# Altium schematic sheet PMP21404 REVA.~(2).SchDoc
size 431 x 279 mm; Date: Not shown in title block; ApprovedBy: Not shown in title block; CheckedBy: Not shown in title block; Author: Not shown in title block; CompanyName: Not shown in title block; Engineer: Not shown in title block; Organization: Not shown in title block; Address1: Not shown in title block; Address2: Not shown in title block; Address3: Not shown in title block; Address4: Not shown in title block; DocumentNumber: 1; Revision: Use project parameter SCH_Rev; SheetNumber: 1; SheetTotal: 1; PageSetup: Record=PageOptions¦CenterHorizontal=True¦CenterVertical=True¦PrintScale=1.00¦XCorrection=1.00¦YCorrection=1.00¦PrintKind=0¦BorderSize=5000000¦LeftOffset=0¦BottomOffset=0¦Orientation=2¦PaperLength=1000¦PaperWidth=1000¦Scale=100¦PaperSource=15¦PrintQuality=600¦MediaType=1¦DitherType=10¦PaperKind=Letter¦PrintScaleMode=1
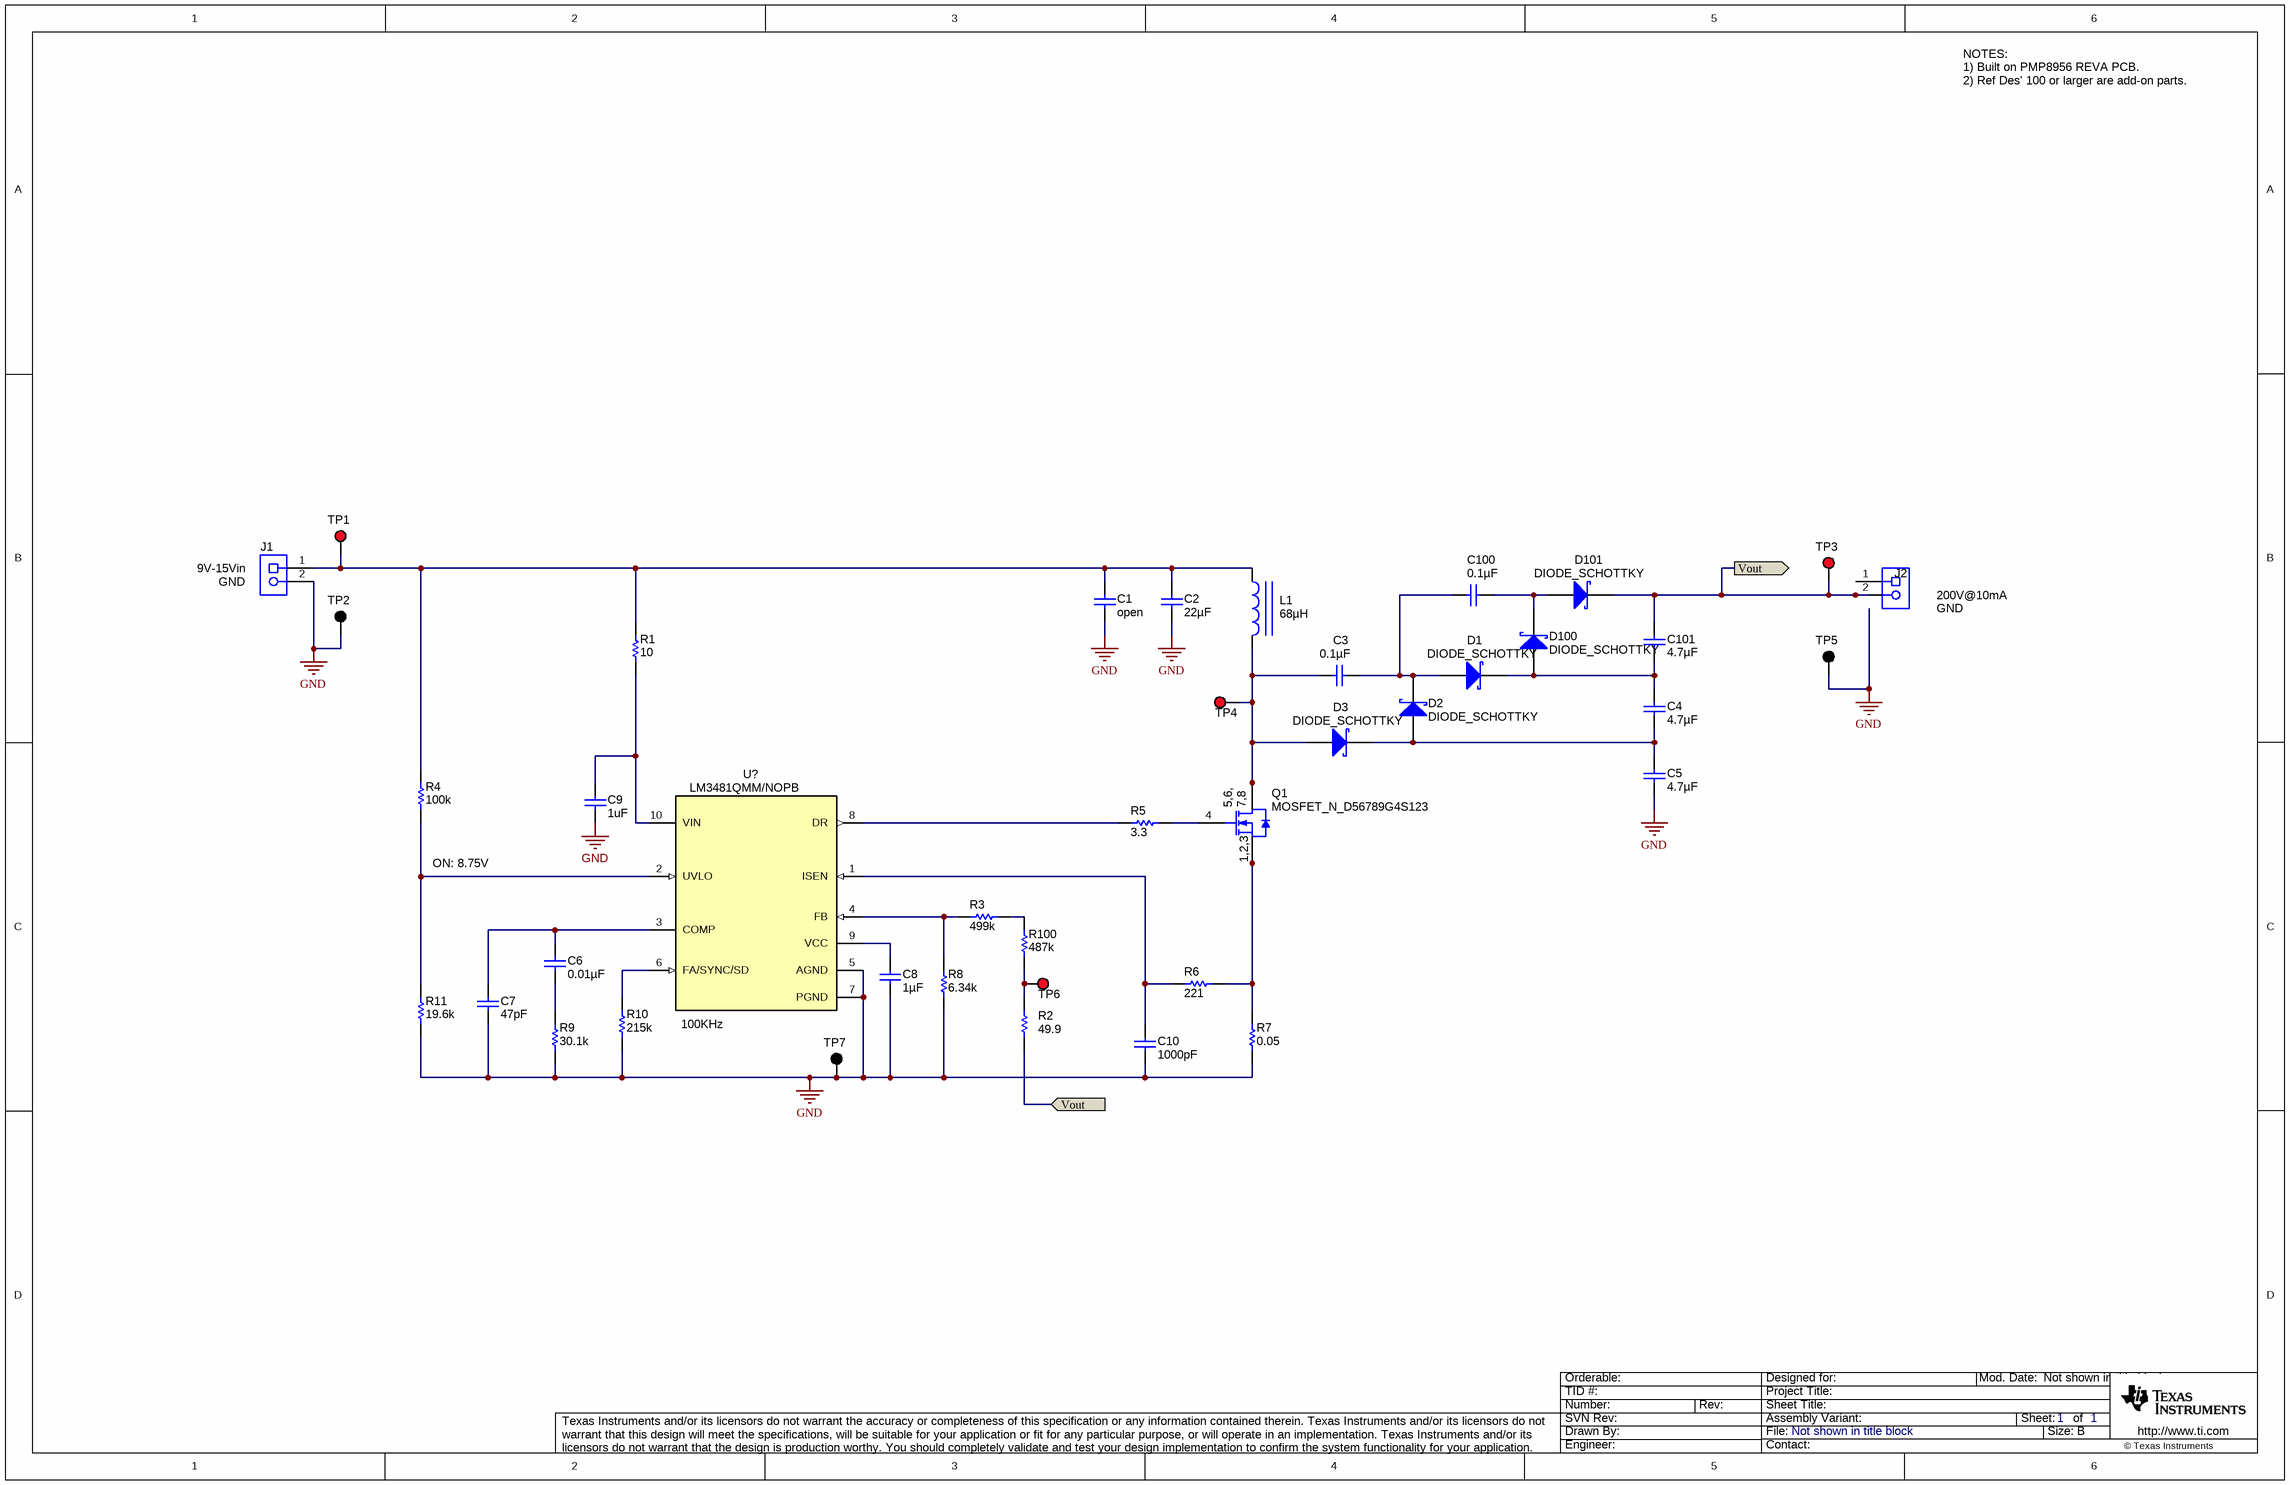
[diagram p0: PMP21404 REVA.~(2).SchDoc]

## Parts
C1  ValueDisplayed: open  [1206L]
C2  ValueDisplayed: 22µF  [1210]  (hidden comment: GRM32ER71E226ME15)
C3  ValueDisplayed: 0.1µF  [0805_HV]  (hidden comment: C2012X7R2A104K)
C4  ValueDisplayed: 4.7µF  [1210]  (hidden comment: C3225X7S2A475M)
C5  ValueDisplayed: 4.7µF  [1210]  (hidden comment: C3225X7S2A475M)
C6  ValueDisplayed: 0.01µF  [0603]  (hidden comment: C1608X7R1H103K)
C7  ValueDisplayed: 47pF  [0603]  (hidden comment: C1608C0G1H470J)
C8  ValueDisplayed: 1µF  [0603L]  (hidden comment: C1608X7R1C105K)
C9  ValueDisplayed: 1uF  [0805L]  (hidden comment: Capacitor)
C10  ValueDisplayed: 1000pF  [0603L]  (hidden comment: C1608X7R1H102K)
C100  ValueDisplayed: 0.1µF  [0805_HV]  (hidden comment: C2012X7R2A104K)
C101  ValueDisplayed: 4.7µF  [1210]  (hidden comment: C3225X7S2A475M)
D1  DIODE_SCHOTTKY  [SOD-123W]
D2  DIODE_SCHOTTKY  [SOD-123W]
D3  DIODE_SCHOTTKY  [SOD-123W]
D100  DIODE_SCHOTTKY  [SOD-123W]
D101  DIODE_SCHOTTKY  [SOD-123W]
J1  Receptacle_2x1  [TERM_BLK_ED555-2DS]  (value not drawn)
J2  Receptacle_2x1  [TERM_BLK_ED555-2DS]  (value not drawn)
L1  ValueDisplayed: 68µH  [CLF7045]  (hidden comment: CLF7045NIT-680M-D)
Q1  MOSFET_N_D56789G4S123  [DNH0008A]
R1  value 10  [0603L]  (hidden comment: Resistor)
R2  value 49.9  [0603L]  (hidden comment: Resistor)
R3  ValueDisplayed: 499k  [0805_HV]  (hidden comment: Resistor)
R4  value 100k  [0603L]  (hidden comment: Resistor)
R5  ValueDisplayed: 3.3  [0603]  (hidden comment: Resistor)
R6  value 221  [0603L]  (hidden comment: Resistor)
R7  value 0.05  [0805L]  (hidden comment: Resistor)
R8  ValueDisplayed: 6.34k  [0603L]  (hidden comment: Resistor)
R9  ValueDisplayed: 30.1k  [0603]  (hidden comment: Resistor)
R10  value 215k  [0603]  (hidden comment: Resistor)
R11  value 19.6k  [0603L]  (hidden comment: Resistor)
R100  ValueDisplayed: 487k  [0805_HV]  (hidden comment: Resistor)
TP1  5000  [Keystone5000]  (value not drawn)
TP2  5001  [Keystone5001]  (value not drawn)
TP3  5000  [Keystone5000]  (value not drawn)
TP4  5000  [Keystone5000]  (value not drawn)
TP5  5001  [Keystone5001]  (value not drawn)
TP6  5000  [Keystone5000]  (value not drawn)
TP7  5001  [Keystone5001]  (value not drawn)
U?  LM3481QMM/NOPB  [DGS0010A_N]

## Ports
Vout

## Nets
GND: C1.2 C2.2 C5.2 C7.2 C8.2 C9.2 C10.2 J1.2 R7.1 R8.1 R9.1 R10.1 R11.1 TP2.1 TP5.1 TP7.1 U?.5(AGND) U?.7(PGND)
Vout: C101.1 D101.1(K) J2.2 R2.1 TP3.1 ; port Vout
NetC1_1: C1.1 C2.1 J1.1 L1.1 R1.2 R4.2 TP1.1
NetC3_1: C3.1 C100.2 D1.2(A) D2.1(K)
NetC3_2: C3.2 D3.2(A) L1.2 Q1.5(D) Q1.6(D) Q1.7(D) Q1.8(D) Q1.9(D) TP4.1
NetC4_1: C4.1 C101.2 D1.1(K) D100.2(A)
NetC4_2: C4.2 C5.1 D2.2(A) D3.1(K)
NetC6_1: C6.1 C7.1 U?.3(COMP)
NetC6_2: C6.2 R9.2
NetC8_1: C8.1 U?.9(VCC)
NetC9_1: C9.1 R1.1 U?.10(VIN)
NetC10_1: C10.1 R6.2 U?.1(ISEN)
NetC100_1: C100.1 D100.1(K) D101.2(A)
NetQ1_1: Q1.1(S) Q1.2(S) Q1.3(S) R6.1 R7.2
NetQ1_4: Q1.4(G) R5.2
NetR2_2: R2.2 R100.1 TP6.1
NetR3_1: R3.1 R8.2 U?.4(FB)
NetR3_2: R3.2 R100.2
NetR4_1: R4.1 R11.2 U?.2(UVLO)
NetR5_1: R5.1 U?.8(DR)
NetR10_2: R10.2 U?.6(FA/SYNC/SD)

Not connected (* = marked no-connect by the designer): J2 1

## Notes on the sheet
- NOTES:
  1) Built on PMP8956 REVA PCB.
  2) Ref Des' 100 or larger are add-on parts.
- (near J1) 9V-15Vin
- (near J1) GND
- 200V@10mA
- GND
- (near R4) ON: 8.75V
- (near U?) 100KHz

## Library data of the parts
C1 = C3216X7R2A104M: CAP, open, 1206; Polarized: N; CompType: Capacitor; U/M: EA; Cap_F: 0.0000001; Tolerance_%: 20; TaMin_C: -55; TaMax_C: 125
C2 = GRM32ER71E226KE15L: CAP, CERM, 22 µF, 25 V, +/- 10%, X7R, 1210; Manufacturer: MuRata; Polarized: N; CompType: Capacitor; Value: 22uF; U/M: EA; Cap_F: 0.000022; Tolerance_%: 10; Value1: Unknown; VDC_V: 25; Value2: 25V; TaMin_C: -55; TaMax_C: 125; AEC Category: Q200
C3 C100 = C2012X7R2A104K: CAP, CERM, 0.1uF, 100V, +/-10%, X7R, 0805; Manufacturer: TDK; Polarized: N; CompType: Capacitor; U/M: EA; Cap_F: 0.0000001; Tolerance_%: 10; ESR_Ohm: 0.0158; Value1: 0.0158 ohm; VDC_V: 100; TaMin_C: -55; TaMax_C: 125; Cap_Case: 0805
C4 C5 C101 = C3225X5R1E106K: CAP, CERM, 4.7uF, 100V, +/-20%, X7S, 1210; Manufacturer: TDK; Polarized: N; CompType: Capacitor; U/M: EA; Cap_F: 0.00001; Tolerance_%: 20; ESR_Ohm: 0.015; Value1: 0.015 ohm; VDC_V: 100; IRMS_A: 3; TaMin_C: -55; TaMax_C: 125
C6 = C1608X7R1H103K: CAP, CERM, 0.01uF, 50V, +/-10%, X7R, 0603; Manufacturer: TDK; Polarized: N; CompType: Capacitor; U/M: EA; Cap_F: 0.00000001; Tolerance_%: 10; ESR_Ohm: 0.0539; Value1: 0.0539 ohm; VDC_V: 50; TaMin_C: -55; TaMax_C: 125
C7 = C1608C0G1H470J: CAP, CERM, 47pF, 50V, +/-5%, C0G/NP0, 0603; Manufacturer: TDK; Polarized: N; CompType: Capacitor; U/M: EA; Cap_F: 0.000000000047; Tolerance_%: 5; ESR_Ohm: 0.22; Value1: 0.22 ohm; VDC_V: 50; TaMin_C: -55; TaMax_C: 125
C8 = C1608X7R1C105K: CAP, CERM, 1uF, 16V, +/-10%, X7R, 0603; Manufacturer: TDK; Polarized: N; CompType: Capacitor; U/M: EA; Cap_F: 0.000001; Tolerance_%: 10; ESR_Ohm: 0.0057; Value1: 0.0057 ohm; VDC_V: 16; TaMin_C: -55; TaMax_C: 125; Cap_Case: 0603
C9 = CMP-0008350-2: CAP, CERM, 1 uF, 50 V, +/- 10%, X7R, 0805; PartNumber: GRM21BR71H105KA12L; Manufacturer: MuRata; Polarized: N; Value: 1uF; U/M: EA; Cap_F: 1µF; Value1: Unknown; VDC_V: 50V; TaMin_C: -55°C; TaMax_C: 125°C; Cap_Case: 0805; AEC Category: Q200; SizeArea_mm2: 2.5; SizeAreaWB_mm2: 6.75; SizeX_mm: 2; SizeY_mm: 1.25; SizeZ_mm: 1.45
C10 = C1608X7R1H102K: CAP, CERM, 1000pF, 50V, +/-10%, X7R, 0603; Manufacturer: TDK; Polarized: N; CompType: Capacitor; U/M: EA; Cap_F: 0.000000001; Tolerance_%: 10; ESR_Ohm: 0.24; Value1: 0.24 ohm; VDC_V: 50; TaMin_C: -55; TaMax_C: 125; Cap_Case: 0603
D1-D3 D100 D101 = CMP-0028782-1: Diode, Schottky, 100 V, 1 A, AEC-Q101, SOD-123W; PartNumber: PMEG10010ELRX; Manufacturer: Nexperia; U/M: EA; Vf_V: 7.7dV; Value: 100V; Value1: 1A; Value2: 0.77V; TJmax_C: 175°C; AEC Category: Q101; AEC Qualified: Y; Green_Lifecycle: Not Set; Green_REACh: Incomplete; SizeArea_mm2: 5.95; SizeAreaWB_mm2: 12.15; SizeX_mm: 3.5; SizeY_mm: 1.7; SizeZ_mm: 1
J1 J2 = CMP-0074913-1: Terminal Block, 3.5mm Pitch, 2x1, TH; PartNumber: ED555/2DS; Manufacturer: On-Shore Technology; Cert_CULUS: Y; CNHeader: False; ContactFinish: Brass; CT: True; Current_A: 6A; Gender: Female; Green_Lifecycle: Active; Green_REACh: Passed; Pitch_mm: 3.5; Row_Count: 1; Shrouded: N; Voltage_V: 150V
L1 = CLF7045T-680M: Inductor, Shielded, Ferrite, 68 µH, 1.1 A, 0.17 ohm, SMD; Manufacturer: TDK; Value: 68uH; Ind_H: 68.0E-6; Imax_A: 1.1; Irms: 0.95A @ 30C rise; Isat: 1.1A @ 10% inductance drop; DCR_ohm: 0.25; Value2: 1.1A; AEC Category: Q200
Q1 = CMP-0000969-2: MOSFET, N-CH, 100 V, 5 A, DNH0008A (VSONP-8); PartNumber: CSD19538Q3A; Manufacturer: Texas Instruments; Alternate Manufacturer: None; U/M: EA; ChType: N; Value: 100V; Value2: 7.2 nC; QgTyp_nC: 7.2; Vgs_V: 20V; IdsMax_A: 5A; AEC Category: Q101; SizeArea_mm2: 10.89; SizeAreaWB_mm2: 18.49; SizeX_mm: 3.3; SizeZ_mm: 0.9
R1 = CMP-0025703-4: RES, 10, 5%, 0.1 W, AEC-Q200 Grade 0, 0603; PartNumber: CRCW060310R0JNEA; Manufacturer: Vishay-Dale; Value_Code: 10R0; Power_W: 100mW; Value2: 0.1W; VDC_V: 75V; TempCo: 200 ppm/C; EIA_Code: E24; AEC Category: Q200; AEC Grade: 0; AEC Qualified: Y; SizeArea_mm2: 1.28; SizeX_mm: 1.6; SizeY_mm: 0.8; SizeZ_mm: 1
R2 = CMP-0022448-4: RES, 49.9, 1%, 0.1 W, AEC-Q200 Grade 0, 0603; PartNumber: CRCW060349R9FKEA; Manufacturer: Vishay-Dale; Value_Code: 49R9; Power_W: 100mW; Value2: 0.1W; VDC_V: 75V; TempCo: 100 ppm/C; EIA_Code: E96; AEC Category: Q200; AEC Grade: 0; AEC Qualified: Y; SizeArea_mm2: 1.28; SizeX_mm: 1.6; SizeY_mm: 0.8; SizeZ_mm: 1
R3 = CMP-0021281-3: RES, 499 k, 1%, 0.125 W, AEC-Q200 Grade 0, 0805; PartNumber: CRCW0805499KFKEA; Manufacturer: Vishay-Dale; Value: 499k; Power_W: 125mW; Value2: 0.125W; VDC_V: 150V; TempCo: 100 ppm/C; EIA_Code: E96; AEC Category: Q200; AEC Qualified: Y; AEC Grade: 0; SizeArea_mm2: 2.5; SizeX_mm: 2; SizeY_mm: 1.25; SizeZ_mm: 1.45
R4 = CMP-0021990-4: RES, 100 k, 1%, 0.1 W, AEC-Q200 Grade 0, 0603; PartNumber: CRCW0603100KFKEA; Manufacturer: Vishay-Dale; Power_W: 100mW; Value2: 0.1W; VDC_V: 75V; TempCo: 100 ppm/C; EIA_Code: E96; AEC Category: Q200; AEC Grade: 0; AEC Qualified: Y; SizeArea_mm2: 1.28; SizeX_mm: 1.6; SizeY_mm: 0.8; SizeZ_mm: 1
R5 = CMP-0025805-4: RES, 3.3, 5%, 0.1 W, AEC-Q200 Grade 0, 0603; PartNumber: CRCW06033R30JNEA; Manufacturer: Vishay-Dale; Value: 3.3; Value_Code: 3R30; Power_W: 100mW; Value2: 0.1W; VDC_V: 75V; TempCo: 200 ppm/C; EIA_Code: E24; AEC Category: Q200; AEC Qualified: Y; AEC Grade: 0; SizeArea_mm2: 1.28; SizeX_mm: 1.6; SizeY_mm: 0.8; SizeZ_mm: 1
R6 = CMP-0022217-5: RES, 221, 1%, 0.1 W, AEC-Q200 Grade 0, 0603; PartNumber: CRCW0603221RFKEA; Manufacturer: Vishay-Dale; Value_Code: 221R; Power_W: 100mW; Value2: 0.1W; VDC_V: 75V; TempCo: 100 ppm/C; EIA_Code: E96; AEC Category: Q200; AEC Grade: 0; AEC Qualified: Y; SizeArea_mm2: 1.28; SizeX_mm: 1.6; SizeY_mm: 0.8; SizeZ_mm: 1
R7 = CMP-0021513-2: RES, 0.05, 1%, 0.25 W, 0805; PartNumber: CRM0805-FW-R050ELF; Manufacturer: Bourns; Value_Code: R050; Power_W: 250mW; Value2: 0.25W; VDC_V: 0V; TempCo: 150 ppm/C; EIA_Code: E96; U/M: EA; AEC Category: Q200; SizeArea_mm2: 2.5; SizeX_mm: 2; SizeY_mm: 1.25; SizeZ_mm: 1.45
R8 = CMP-0022560-4: RES, 6.34 k, 1%, 0.1 W, AEC-Q200 Grade 0, 0603; PartNumber: CRCW06036K34FKEA; Manufacturer: Vishay-Dale; Value: 6.34k; Value_Code: 6k34; Power_W: 100mW; Value2: 0.1W; VDC_V: 75V; TempCo: 100 ppm/C; EIA_Code: E96; AEC Category: Q200; AEC Qualified: Y; AEC Grade: 0; SizeArea_mm2: 1.28; SizeX_mm: 1.6; SizeY_mm: 0.8; SizeZ_mm: 1
R9 = CMP-0022324-4: RES, 30.1 k, 1%, 0.1 W, AEC-Q200 Grade 0, 0603; PartNumber: CRCW060330K1FKEA; Manufacturer: Vishay-Dale; Value: 30.1k; Value_Code: 30k1; Power_W: 100mW; Value2: 0.1W; VDC_V: 75V; TempCo: 100 ppm/C; EIA_Code: E96; AEC Category: Q200; AEC Qualified: Y; AEC Grade: 0; SizeArea_mm2: 1.28; SizeX_mm: 1.6; SizeY_mm: 0.8; SizeZ_mm: 1
R10 = CMP-0022210-4: RES, 215 k, 1%, 0.1 W, AEC-Q200 Grade 0, 0603; PartNumber: CRCW0603215KFKEA; Manufacturer: Vishay-Dale; Power_W: 100mW; Value2: 0.1W; VDC_V: 75V; TempCo: 100 ppm/C; EIA_Code: E96; AEC Category: Q200; AEC Grade: 0; AEC Qualified: Y; SizeArea_mm2: 1.28; SizeX_mm: 1.6; SizeY_mm: 0.8; SizeZ_mm: 1
R11 = CMP-0022106-4: RES, 19.6 k, 1%, 0.1 W, AEC-Q200 Grade 0, 0603; PartNumber: CRCW060319K6FKEA; Manufacturer: Vishay-Dale; Value_Code: 19k6; Power_W: 100mW; Value2: 0.1W; VDC_V: 75V; TempCo: 100 ppm/C; EIA_Code: E96; AEC Category: Q200; AEC Grade: 0; AEC Qualified: Y; SizeArea_mm2: 1.28; SizeX_mm: 1.6; SizeY_mm: 0.8; SizeZ_mm: 1
R100 = CMP-0021277-3: RES, 487 k, 1%, 0.125 W, AEC-Q200 Grade 0, 0805; PartNumber: CRCW0805487KFKEA; Manufacturer: Vishay-Dale; Value: 487k; Power_W: 125mW; Value2: 0.125W; VDC_V: 150V; TempCo: 100 ppm/C; EIA_Code: E96; AEC Category: Q200; AEC Qualified: Y; AEC Grade: 0; SizeArea_mm2: 2.5; SizeX_mm: 2; SizeY_mm: 1.25; SizeZ_mm: 1.45
TP1 TP3 TP4 TP6 = CMP-0055137-1: Test Point, Miniature, Red, TH; Manufacturer: Keystone; CNHeader: FALSE; ContactFinish: Silver; CT: TRUE; Green_Lifecycle: Active; Green_REACh: Passed
TP2 TP5 TP7 = CMP-0055138-1: Test Point, Miniature, Black, TH; Manufacturer: Keystone; CNHeader: FALSE; ContactFinish: Silver; CT: TRUE; Green_Lifecycle: Active; Green_REACh: Passed
U? = CMP-0071928-2: High Efficiency Low-Side N-Channel Controller for Switching Regulators, AEC-Q100 Grade 1, 10-pin Mini SOIC, 1000 Reel; Manufacturer: Texas Instruments; Alternate PartNumber: LM3481QMMX/NOPB; CompType: IC; AEC Category: Q200; AEC Qualified: Y; SizeAreaWB_mm2: 23.6; SizeArea_mm2: 14.7; SizeX_mm: 4.9; SizeY_mm: 3; SizeZ_mm: 1.1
